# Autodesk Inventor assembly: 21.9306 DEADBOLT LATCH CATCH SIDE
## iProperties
Created: 2012-07
Part Number: 21.9306 DEADBOLT LATCH CATCH SIDE
Document SubType Name: Assembly
Designer: Administrator
Mass: 47.0586 g
Surface Area: 52.9189 cm^2
Volume: 6.77681 cm^3
Density: 6.94407 g/cm^3
Author: Administrator
